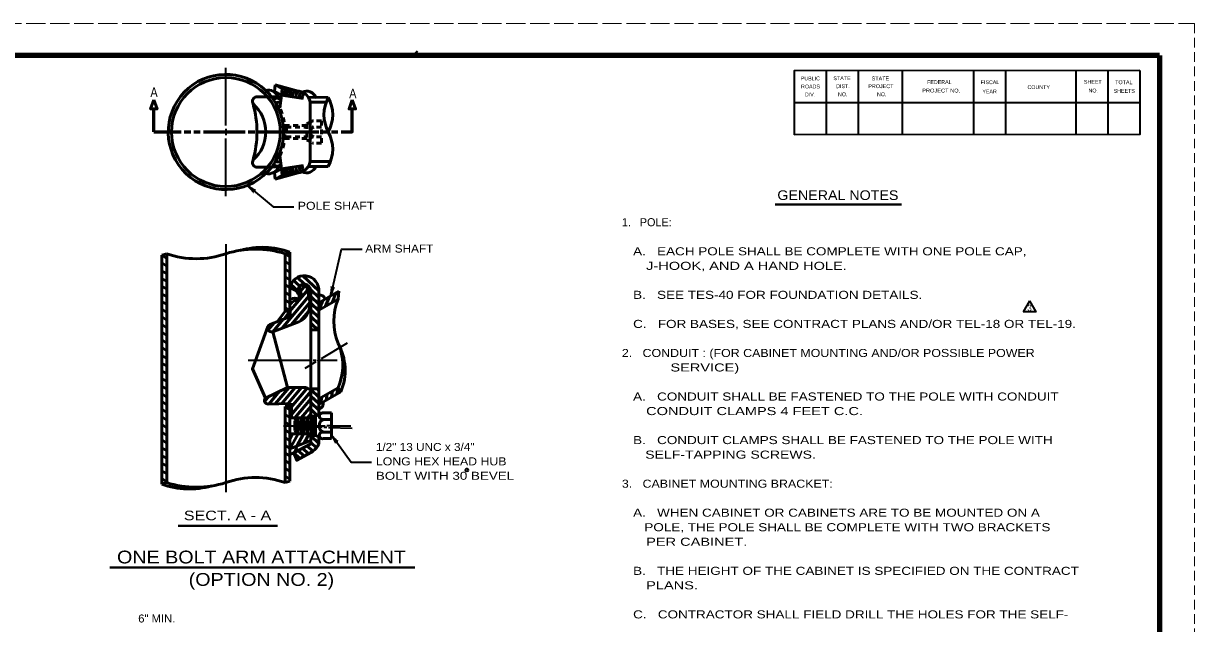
# Model space of a CAD drawing. Extents: x 6488 to 7168, y 276 to 716.
# Drawn here: x 6801.8 to 7167.7, y 528.6 to 716 of the extents above; entities that cross this region are included whole.
import ezdxf
from ezdxf.enums import TextEntityAlignment as Align

# ---------------------------------------------------------------- set-up
doc = ezdxf.new("R2010")
doc.units = 0
for name, pattern in [('LONG_DASHED', [7.5, 6, -1.5]), ('MEDIUM_DASHED', [4.5, 3, -1.5]), ('SHORT_DASHED', [2.7, 1.5, -1.2])]:
    doc.linetypes.add(name, pattern=pattern)
doc.layers.add('1', color=7, linetype='Continuous', lineweight=35)
doc.layers.add('61', color=7, linetype='Continuous', lineweight=35)

msp = doc.modelspace()

# ---------------------------------------------------------------- linework, layer by layer
at = {"layer": '1', "linetype": 'MEDIUM_DASHED', "lineweight": 13}
msp.add_line((7167.663, 716.04), (7167.643, 276.02), dxfattribs=at)
at = {"layer": '1', "linetype": 'SHORT_DASHED', "lineweight": 53}
for p, q in [((6924.843, 706.832), (6924.405, 707.27)), ((6890.36, 684.641), (6891.606, 685.264)), ((6890.36, 684.641), (6890.36, 679.641)), ((6894.86, 685.641), (6892.36, 685.641)), ((6894.86, 685.641), (6894.86, 678.641)), ((6883.402, 684.141), (6882.964, 683.703)), ((6883.402, 684.141), (6890.36, 684.141)), ((6883.951, 683.641), (6890.36, 683.641)), ((6883.951, 683.641), (6883.953, 680.641)), ((6883.953, 680.641), (6890.36, 680.641)), ((6894.86, 683.641), (6892.36, 683.641)), ((6894.86, 680.641), (6892.36, 680.641)), ((6883.405, 680.141), (6890.36, 680.141)), ((6890.36, 679.641), (6891.606, 679.018)), ((6894.86, 678.641), (6892.36, 678.641))]:
    msp.add_line(p, q, dxfattribs=at)
at = {"layer": '1'}
for p, q in [((6865.036, 684.141), (6865.036, 702.127)), ((6865.036, 683.141), (6865.036, 681.141)), ((6865.036, 662.127), (6865.036, 680.141)), ((6865.036, 647.127), (6865.036, 569.627)), ((7116.109, 629.377), (7114.109, 625.913)), ((6894.956, 611.435), (6903.03, 616.279)), ((6893.67, 610.663), (6894.527, 611.178)), ((6872.026, 610.877), (6891.776, 610.877)), ((6889.811, 608.348), (6893.241, 610.406)), ((6892.276, 610.877), (6893.276, 610.877)), ((6893.776, 610.877), (6899.776, 610.877)), ((6883.036, 590.377), (6896.026, 590.377)), ((6883.036, 590.377), (6895.084, 589.957)), ((6895.584, 589.939), (6896.587, 589.904)), ((6897.526, 590.377), (6896.526, 590.377)), ((6897.086, 589.887), (6904.526, 589.627)), ((6898.026, 590.377), (6904.026, 590.377))]:
    msp.add_line(p, q, dxfattribs=at)
at = {"layer": '1', "lineweight": 53}
for p, q in [((6880.456, 696.846), (6880.213, 694.861)), ((6882.622, 695.596), (6880.456, 696.846)), ((6880.456, 696.846), (6887.573, 694.9)), ((6882.378, 693.611), (6882.622, 695.596)), ((6882.622, 695.596), (6887.573, 694.9)), ((6874.536, 693.141), (6878.016, 693.102)), ((6877.475, 695.136), (6877.282, 695.088)), ((6878.266, 693.1), (6879.062, 693.091)), ((6879.311, 693.088), (6882.309, 693.055)), ((6881.455, 693.064), (6879.312, 693.088)), ((6882.378, 693.611), (6880.213, 694.861)), ((6881.89, 689.641), (6882.378, 693.611)), ((6882.378, 693.611), (6889.31, 692.637)), ((6890.778, 692.961), (6897.036, 692.891)), ((6893.143, 692.934), (6890.778, 692.961)), ((6891.36, 691.399), (6891.36, 672.899)), ((6881.903, 674.641), (6882.391, 670.671)), ((6874.536, 671.141), (6878.04, 671.18)), ((6878.29, 671.183), (6879.083, 671.192)), ((6879.333, 671.194), (6882.322, 671.228)), ((6881.478, 671.21), (6879.335, 671.186)), ((6882.391, 670.671), (6880.226, 669.421)), ((6882.391, 670.671), (6889.323, 671.645)), ((6882.391, 670.671), (6882.635, 668.686)), ((6893.111, 671.325), (6890.746, 671.298)), ((6890.768, 671.322), (6897.036, 671.391)), ((6877.497, 669.135), (6877.305, 669.183)), ((6880.226, 669.421), (6880.469, 667.436)), ((6880.469, 667.436), (6887.586, 669.382)), ((6882.635, 668.686), (6880.469, 667.436)), ((6882.635, 668.686), (6887.586, 669.382)), ((6846.536, 644.127), (6845.036, 643.627)), ((6846.536, 644.127), (6846.536, 572.627)), ((6883.536, 644.127), (6885.036, 644.627)), ((6883.536, 644.127), (6883.536, 626.127)), ((6883.536, 644.127), (6885.036, 643.127)), ((6885.036, 644.627), (6885.036, 633.318)), ((6845.036, 643.627), (6845.036, 572.127)), ((6845.036, 643.627), (6846.536, 642.627)), ((6845.036, 641.223), (6846.536, 640.223)), ((6883.536, 641.723), (6885.036, 640.723)), ((6845.036, 638.819), (6846.536, 637.819)), ((6883.536, 639.319), (6885.036, 638.319)), ((6883.536, 636.916), (6885.036, 635.916)), ((6887.399, 636.72), (6889.619, 634.607)), ((6889.045, 637.224), (6894.026, 632.485)), ((6845.036, 636.416), (6846.536, 635.416)), ((6845.036, 634.012), (6846.536, 633.012)), ((6883.536, 634.512), (6885.036, 633.512)), ((6885.036, 629.651), (6885.036, 633.318)), ((6885.036, 633.318), (6885.036, 629.894)), ((6885.366, 634.513), (6887.4, 632.578)), ((6886.197, 635.793), (6888.019, 634.06)), ((6887.255, 632.238), (6888.035, 634.074)), ((6888.035, 633.824), (6888.718, 630.54)), ((6888.328, 632.415), (6889.807, 634.187)), ((6890.286, 633.723), (6891.186, 629.826)), ((6845.036, 631.608), (6846.536, 630.608)), ((6882.54, 620.795), (6890.945, 630.869)), ((6883.536, 632.108), (6885.036, 631.108)), ((6883.536, 629.704), (6885.036, 628.704)), ((6885.036, 626.127), (6890.522, 632.703)), ((6885.036, 629.752), (6885.036, 626.127)), ((6885.133, 629.733), (6885.036, 629.651)), ((6891.524, 632.796), (6894.026, 630.415)), ((6891.526, 630.723), (6894.026, 628.344)), ((6894.026, 628.781), (6900.305, 632.406)), ((6894.026, 628.781), (6894.026, 632.249)), ((6894.026, 626.472), (6900.088, 629.972)), ((6894.026, 626.472), (6895.273, 629.501)), ((6896.154, 627.7), (6897.4, 630.73)), ((6898.281, 628.929), (6899.528, 631.958)), ((6900.305, 632.406), (6900.088, 629.972)), ((6845.036, 629.204), (6846.536, 628.204)), ((6845.036, 626.801), (6846.536, 625.801)), ((6883.536, 626.127), (6881.129, 622.933)), ((6883.536, 627.301), (6885.036, 626.301)), ((6885.401, 621.881), (6891.369, 629.035)), ((6888.381, 623.112), (6890.872, 626.098)), ((6891.526, 628.652), (6894.026, 626.274)), ((6891.526, 626.582), (6894.026, 624.204)), ((6894.026, 620.377), (6894.026, 628.781)), ((6845.036, 624.397), (6846.536, 623.397)), ((6845.036, 621.993), (6846.536, 620.993)), ((6878.288, 620.381), (6880.087, 622.537)), ((6878.792, 622.044), (6884.165, 624.086)), ((6879.68, 619.708), (6882.947, 623.623)), ((6879.68, 619.707), (6887.857, 622.815)), ((6891.526, 624.512), (6894.026, 622.133)), ((6891.526, 622.441), (6894.026, 620.063)), ((6845.036, 619.589), (6846.536, 618.589)), ((6884.286, 602.377), (6879.68, 619.707)), ((6891.526, 620.377), (6894.026, 620.377)), ((6894.026, 595.587), (6894.026, 620.377)), ((6845.036, 617.186), (6846.536, 616.185)), ((6845.036, 614.782), (6846.536, 613.782)), ((6845.036, 612.378), (6846.536, 611.378)), ((6845.036, 609.974), (6846.536, 608.974)), ((6845.036, 607.57), (6846.536, 606.57)), ((6845.036, 605.167), (6846.536, 604.166)), ((6845.036, 602.763), (6846.536, 601.763)), ((6845.036, 600.359), (6846.536, 599.359)), ((6884.286, 602.377), (6877.398, 599.017)), ((6878.439, 597.147), (6881.785, 601.157)), ((6880.451, 597.217), (6884.756, 602.377)), ((6882.463, 597.287), (6886.71, 602.377)), ((6884.286, 602.377), (6889.46, 602.377)), ((6884.475, 597.357), (6888.663, 602.377)), ((6885.536, 596.287), (6890.442, 602.168)), ((6885.536, 593.946), (6891.526, 601.126)), ((6891.526, 601.877), (6894.026, 601.877)), ((6891.526, 601.737), (6894.026, 599.359)), ((6893.555, 601.877), (6894.026, 601.429)), ((6894.026, 598.759), (6900.088, 602.259)), ((6894.026, 597.027), (6900.954, 601.027)), ((6896.678, 600.29), (6896.324, 598.354)), ((6898.383, 601.275), (6898.029, 599.338)), ((6900.088, 602.259), (6899.734, 600.323)), ((6900.088, 602.259), (6900.954, 601.027)), ((6845.036, 597.955), (6846.536, 596.955)), ((6877.175, 597.974), (6878.491, 599.551)), ((6885.036, 597.377), (6878.29, 597.141)), ((6885.536, 597.395), (6885.536, 592.877)), ((6886.597, 592.877), (6891.526, 598.784)), ((6888.551, 592.877), (6891.526, 596.443)), ((6891.526, 599.667), (6894.026, 597.288)), ((6891.526, 597.596), (6894.026, 595.218)), ((6894.026, 597.027), (6895.357, 597.795)), ((6894.026, 595.587), (6894.026, 597.027)), ((6894.974, 599.306), (6894.619, 597.37)), ((6845.036, 595.552), (6846.536, 594.552)), ((6845.036, 593.148), (6846.536, 592.148)), ((6883.536, 596.377), (6883.536, 572.627)), ((6883.536, 596.377), (6885.036, 596.377)), ((6883.536, 596.324), (6885.036, 595.324)), ((6883.536, 593.92), (6885.036, 592.92)), ((6885.036, 596.377), (6885.036, 583.127)), ((6885.036, 592.877), (6893.026, 592.877)), ((6886.526, 591.877), (6887.526, 592.877)), ((6887.526, 592.877), (6887.526, 587.877)), ((6888.526, 592.877), (6888.526, 587.877)), ((6889.526, 592.877), (6889.526, 587.877)), ((6890.505, 592.877), (6891.526, 594.101)), ((6890.526, 592.877), (6890.526, 587.877)), ((6891.526, 595.526), (6893.56, 593.591)), ((6893.026, 593.377), (6891.526, 593.377)), ((6891.526, 592.877), (6891.526, 587.877)), ((6892.526, 592.877), (6892.526, 587.877)), ((6893.026, 593.377), (6894.417, 593.933)), ((6893.026, 593.377), (6893.026, 587.377)), ((6894.026, 593.777), (6894.026, 595.587)), ((6898.026, 594.377), (6895.526, 594.377)), ((6898.026, 594.377), (6898.026, 586.377)), ((6845.036, 590.744), (6846.536, 589.744)), ((6883.536, 591.517), (6885.036, 590.517)), ((6883.536, 589.113), (6885.036, 588.113)), ((6886.526, 591.877), (6886.526, 588.877)), ((6888.026, 591.877), (6888.026, 588.877)), ((6889.026, 591.877), (6889.026, 588.877)), ((6890.026, 591.877), (6890.026, 588.877)), ((6891.026, 591.877), (6891.026, 588.877)), ((6892.026, 591.877), (6892.026, 588.877)), ((6893.026, 591.877), (6893.026, 588.877)), ((6898.026, 592.377), (6895.526, 592.377)), ((6845.036, 588.34), (6846.536, 587.34)), ((6845.036, 585.937), (6846.536, 584.937)), ((6883.536, 586.709), (6885.036, 585.709)), ((6885.036, 587.877), (6893.026, 587.877)), ((6885.036, 583.127), (6887.6, 587.877)), ((6885.036, 586.285), (6885.895, 587.877)), ((6885.036, 583.127), (6891.526, 585.749)), ((6886.526, 588.877), (6887.526, 587.877)), ((6887.216, 584.008), (6889.305, 587.877)), ((6889.396, 584.889), (6891.009, 587.877)), ((6891.526, 584.749), (6891.526, 587.877)), ((6893.026, 587.377), (6891.526, 587.377)), ((6891.526, 587.244), (6894.026, 584.866)), ((6893.026, 587.377), (6894.369, 586.84)), ((6894.026, 584.749), (6894.026, 586.977)), ((6898.026, 588.377), (6895.526, 588.377)), ((6898.026, 586.377), (6895.526, 586.377)), ((6845.036, 583.533), (6846.536, 582.533)), ((6883.536, 584.305), (6885.036, 583.305)), ((6883.536, 581.902), (6885.036, 580.901)), ((6885.036, 583.127), (6887.038, 583.936)), ((6885.036, 583.305), (6885.036, 573.127)), ((6885.036, 581.511), (6885.036, 583.127)), ((6886.228, 581.933), (6888.113, 580.14)), ((6887.624, 582.675), (6889.488, 580.902)), ((6889.02, 583.417), (6890.863, 581.664)), ((6890.416, 584.159), (6892.226, 582.438)), ((6891.526, 585.174), (6893.315, 583.472)), ((6845.036, 581.129), (6846.536, 580.129)), ((6845.036, 578.725), (6846.536, 577.725)), ((6883.536, 579.498), (6885.036, 578.498)), ((6845.036, 576.322), (6846.536, 575.321)), ((6883.536, 577.094), (6885.036, 576.094)), ((6883.536, 574.69), (6885.036, 573.69)), ((6845.036, 573.918), (6846.536, 572.918)), ((6846.536, 572.627), (6845.036, 572.127)), ((6883.536, 572.627), (6885.036, 573.127))]:
    msp.add_line(p, q, dxfattribs=at)
at = {"layer": '1', "lineweight": 60}
for p, q in [((6842.534, 682.141), (6842.534, 689.322)), ((6842.534, 682.141), (6851.034, 682.141)), ((6852.034, 682.141), (6854.034, 682.141)), ((6855.034, 682.141), (6857.034, 682.141)), ((6858.034, 682.141), (6871.034, 682.141)), ((6872.034, 682.141), (6874.034, 682.141)), ((6875.034, 682.141), (6877.034, 682.141)), ((6878.034, 682.141), (6894.034, 682.141)), ((6895.034, 682.141), (6897.034, 682.141)), ((6898.034, 682.141), (6900.034, 682.141))]:
    msp.add_line(p, q, dxfattribs=at)
at = {"layer": '1', "linetype": 'LONG_DASHED', "lineweight": 53}
for p, q in [((6896.36, 691.399), (6891.36, 691.399)), ((6897.717, 672.899), (6891.36, 672.899))]:
    msp.add_line(p, q, dxfattribs=at)
at = {"layer": '1', "lineweight": 40}
for p, q in [((7036.624, 659.512), (7076.064, 659.512)), ((6850.157, 559.125), (6881.136, 559.125)), ((6828.823, 546.105), (6924.037, 546.105))]:
    msp.add_line(p, q, dxfattribs=at)
at = {"layer": '1', "lineweight": 53}
for points in [[(6842.534, 692.141), (6843.56, 689.322), (6841.508, 689.322)], [(6904.534, 692.141), (6903.508, 689.322), (6905.56, 689.322)]]:
    msp.add_lwpolyline(points, close=True, dxfattribs=at)
at = {"layer": '1', "lineweight": 60}
msp.add_lwpolyline([(6901.034, 682.141), (6904.534, 682.141), (6904.534, 689.322)], dxfattribs=at)
at = {"layer": '1'}
for points in [[(6871.766, 665.433), (6879.767, 658.81), (6886.299, 658.81)], [(6897.787, 630.953), (6901.149, 645.491), (6907.608, 645.491)], [(7116.109, 629.377), (7118.109, 625.913), (7114.109, 625.913)], [(6898.026, 587.505), (6904.139, 578.964), (6910.524, 578.964)]]:
    msp.add_lwpolyline(points, dxfattribs=at)
at = {"layer": '1', "lineweight": 53}
for points in [[(6885.036, 628.258), (6885.036, 629.651), (6885.133, 629.733)], [(6891.526, 592.877), (6891.526, 620.377), (6891.526, 632.249)], [(6896.021, 629.933), (6894.026, 628.781), (6894.026, 631.105)], [(6896.021, 629.933), (6894.026, 628.781), (6894.026, 631.105)], [(6883.536, 626.127), (6885.036, 626.127), (6883.23, 623.731)], [(6877.398, 599.017), (6873.33, 608.153), (6878.105, 621.371)], [(6891.526, 584.749), (6886.228, 581.933), (6887.165, 579.615), (6891.538, 582.039)]]:
    msp.add_lwpolyline(points, dxfattribs=at)
msp.add_circle((6865.034, 682.127), 17, dxfattribs=at)
at = {"layer": '1'}
msp.add_circle((6940.276, 576.56), 0.437, dxfattribs=at)
at = {"layer": '1', "lineweight": 53}
for centre, radius, start, end in [((6865.034, 682.127), 18, 46.29439, 46.29432), ((6878.215, 691.707), 3.512, 22.73321, 102.24022), ((6884.611, 693.742), 1.627, 117.67481, 178.09117), ((6874.924, 691.622), 1.568, 104.31597, 207.75905), ((6865.034, 682.127), 18, 37.51322, 46.29439), ((6881.024, 690.83), 1.87, 59.13184, 120.50976), ((6885.482, 693.614), 1.627, 117.67481, 178.09117), ((6886.416, 693.388), 1.627, 117.67481, 178.09117), ((6887.415, 693.259), 1.627, 117.67481, 178.09117), ((6888.511, 693.162), 1.627, 117.67481, 178.09117), ((6887.256, 690.759), 4.154, 66.70777, 85.61624), ((6889.607, 693.065), 1.627, 126.56498, 178.09117), ((6890.477, 692.775), 1.627, 130.83621, 173.17119), ((6890.246, 691.749), 3.13, 22.24909, 115.50855), ((6887.256, 690.759), 4.154, 32.00963, 66.70778), ((6887.256, 690.759), 4.154, 8.85834, 66.70714), ((6906.919, 687.514), 11.251, 151.4518, 208.52599), ((6887.148, 687.514), 11.251, 331.47401, 28.5482), ((6865.909, 682.141), 11.607, 311.07568, 48.92433), ((6842.526, 682.141), 32.22, 344.24246, 15.75754), ((6881.46, 690.23), 1.196, 70.78315, 120.86396), ((6881.595, 689.776), 0.281, 74.21707, 117.92319), ((6887.151, 676.764), 11.251, 331.47401, 28.5482), ((6874.924, 672.661), 1.568, 152.24095, 255.68403), ((6881.595, 674.412), 0.281, 242.07681, 285.78293), ((6878.239, 672.567), 3.512, 257.75978, 337.26679), ((6865.057, 682.147), 18, 313.70561, 322.48678), ((6881.024, 673.358), 1.87, 239.49024, 300.86816), ((6881.46, 673.958), 1.196, 239.13604, 289.21685), ((6884.611, 670.51), 1.627, 181.90883, 242.32519), ((6885.482, 670.639), 1.627, 181.90883, 242.32519), ((6886.416, 670.864), 1.627, 181.90883, 242.32519), ((6887.415, 670.993), 1.627, 181.90883, 242.32519), ((6888.511, 671.09), 1.627, 181.90883, 242.32519), ((6887.256, 673.538), 4.154, 274.38376, 351.14166), ((6889.607, 671.187), 1.627, 181.90883, 233.43502), ((6890.477, 671.477), 1.627, 186.82881, 229.16379), ((6890.214, 672.51), 3.13, 244.49145, 337.75091), ((6887.224, 673.5), 4.154, 293.29223, 327.99037), ((6855.786, 670.387), 27.841, 250.595, 289.40499), ((6874.286, 615.086), 30.478, 72.33239, 107.66762), ((6876.465, 620.646), 25.467, 70.33208, 105.78399), ((6889.524, 632.722), 4.527, 354.00383, 172.43749), ((6884.874, 630.166), 3.156, 352.12634, 87.06139), ((6889.442, 632.514), 2.101, 352.76664, 132.03252), ((6889.126, 633.003), 1.366, 31.83455, 143.01959), ((6887.884, 626.251), 3.484, 88.08418, 144.83546), ((6886.567, 627.946), 2.292, 51.26202, 128.73798), ((6886.567, 627.946), 2.292, 51.26202, 128.73798), ((6884.994, 628.47), 6.339, 296.85326, 12.34881), ((6894.525, 629.67), 1.519, 9.96701, 109.19406), ((6894.525, 629.67), 1.519, 9.96701, 109.19406), ((6917.956, 623.044), 19.164, 158.80598, 201.19401), ((6883.663, 625.507), 1.507, 289.47536, 24.31453), ((6879.42, 620.946), 1.266, 119.78112, 281.82632), ((6884.947, 607.677), 17.334, 337.43907, 29.13126), ((6884.28, 609.26), 17.289, 336.11327, 17.19125), ((6889.373, 599.563), 2.815, 40.11472, 91.77534), ((6878.276, 598.285), 1.144, 140.1661, 270.70249), ((6893.667, 597.309), 1.759, 281.77703, 16.07576), ((6895.283, 593.377), 1.029, 76.31896, 283.68104), ((6896.263, 590.377), 2.132, 110.23854, 249.76146), ((6895.255, 587.377), 1.036, 74.83777, 285.16224), ((6884.919, 583.647), 2.139, 273.13893, 7.7568), ((6889.427, 586.474), 4.912, 295.45694, 339.44803), ((6853.607, 596.108), 25.467, 250.33208, 285.78399), ((6855.786, 601.668), 30.478, 252.33239, 287.66762), ((6874.286, 546.368), 27.841, 70.595, 109.40499)]:
    msp.add_arc(centre, radius, start, end, dxfattribs=at)
at = {"layer": '1', "linetype": 'SHORT_DASHED', "lineweight": 53}
for centre, radius, start, end in [((6865.315, 682.127), 18.199, 335.7124, 24.38628), ((6892.388, 684.641), 1, 91.64956, 268.35044), ((6892.388, 679.641), 1, 91.64956, 268.35044), ((6893.073, 682.141), 1.661, 115.42575, 244.57425)]:
    msp.add_arc(centre, radius, start, end, dxfattribs=at)
at = {"layer": '1', "lineweight": 40}
for centre, major_axis, ratio, start_param, end_param in [((6872.494, 664.556), (1.241, -1.255), 0.07063, 6.2823074, 8.5597026), ((6872.782, 664.95), (-1.475, 1.018), 0.122415, 0.8963533, 3.1415927), ((6897.764, 632.078), (-0.25, -1.775), 0.122415, 0.8963533, 3.1415927), ((6898.246, 631.997), (0.567, 1.672), 0.07063, 6.2823074, 8.5597026), ((6898.506, 586.471), (0.879, -1.531), 0.07063, 6.2823074, 8.5597026), ((6898.886, 586.778), (-1.166, 1.361), 0.122415, 0.8963533, 3.1415927)]:
    msp.add_ellipse(centre, major_axis=major_axis, ratio=ratio, start_param=start_param, end_param=end_param, dxfattribs=at)
at = {"layer": '61', "linetype": 'LONG_DASHED', "lineweight": 13}
msp.add_line((6487.643, 716.04), (7167.663, 716.04), dxfattribs=at)
at = {"layer": '61', "lineweight": 158}
msp.add_line((7156.683, 706.04), (7156.703, 286), dxfattribs=at)
at = {"layer": '61'}
for p, q in [((7052.603, 701.28), (7052.603, 681.28)), ((7062.603, 701.28), (7062.603, 681.28)), ((7076.283, 701.28), (7076.283, 681.28)), ((7098.603, 701.28), (7098.603, 681.28)), ((7108.603, 701.28), (7108.603, 681.28)), ((7130.583, 701.3), (7130.583, 681.3)), ((7140.583, 701.3), (7140.583, 681.3)), ((7150.603, 691.26), (7042.583, 691.28))]:
    msp.add_line(p, q, dxfattribs=at)
at = {"layer": '61', "lineweight": 158}
msp.add_lwpolyline([(7156.683, 706.04), (6517.643, 706.04), (6517.643, 286.02)], dxfattribs=at)
at = {"layer": '61'}
for points in [[(7150.583, 701.3), (7042.603, 701.28), (7042.603, 681.28)], [(7150.583, 701.3), (7150.583, 681.3), (7042.603, 681.28)]]:
    msp.add_lwpolyline(points, dxfattribs=at)

# ---------------------------------------------------------------- texts
at = {"layer": '1'}
for s, height, width, p in [('A', 3, 0.85, (6841.45, 693.059)), ('A', 3, 0.85, (6903.558, 692.672)), ('GENERAL NOTES', 3.024, 1.1, (7037.324, 660.892)), ('POLE SHAFT', 2.5, 1.15, (6887.499, 657.834)), ('ARM SHAFT', 2.5, 1.1, (6908.589, 644.479)), ('   A.   EACH POLE SHALL BE COMPLETE WITH ONE POLE CAP,', 2.52, 1.25, (6988.744, 643.612)), ('      J-HOOK, AND A HAND HOLE.', 2.52, 1.35, (6988.744, 639.072)), ('   B.   SEE TES-40 FOR FOUNDATION DETAILS.', 2.52, 1.25, (6988.744, 630.012)), ('3', 2, 0.9, (7115.441, 626.181)), ('   C.   FOR BASES, SEE CONTRACT PLANS AND/OR TEL-18 OR TEL-19.', 2.52, 1.25, (6988.744, 620.932)), ('2.   CONDUIT : (FOR CABINET MOUNTING AND/OR POSSIBLE POWER', 2.52, 1.15, (6988.744, 611.852)), ('            SERVICE)', 2.52, 1.35, (6988.744, 607.332)), ('   A.   CONDUIT SHALL BE FASTENED TO THE POLE WITH CONDUIT', 2.52, 1.25, (6988.744, 598.252)), ('      CONDUIT CLAMPS 4 FEET C.C.', 2.52, 1.35, (6988.744, 593.712)), ('   B.   CONDUIT CLAMPS SHALL BE FASTENED TO THE POLE WITH', 2.52, 1.25, (6988.744, 584.652)), ('1/2" 13 UNC x 3/4"', 2.5, 1.1, (6911.894, 582.511)), ('      SELF-TAPPING SCREWS.', 2.52, 1.3, (6988.744, 580.112)), ('LONG HEX HEAD HUB', 2.5, 1.15, (6911.894, 578.011)), ('BOLT WITH 30 BEVEL', 2.5, 1.25, (6911.894, 573.511)), ('3.   CABINET MOUNTING BRACKET:', 2.52, 1.15, (6988.744, 571.032)), ('SECT. A - A', 3, 1.25, (6851.898, 560.867)), ('   A.   WHEN CABINET OR CABINETS ARE TO BE MOUNTED ON A', 2.52, 1.25, (6988.744, 561.972)), ('      POLE, THE POLE SHALL BE COMPLETE WITH TWO BRACKETS', 2.52, 1.25, (6988.744, 557.432)), ('      PER CABINET.', 2.52, 1.35, (6988.744, 552.892)), ('   B.   THE HEIGHT OF THE CABINET IS SPECIFIED ON THE CONTRACT', 2.52, 1.25, (6988.744, 543.812)), ('      PLANS.', 2.52, 1.35, (6988.744, 539.292)), ('6" MIN.', 2.5, 1.05, (6837.649, 528.941)), ('   C.   CONTRACTOR SHALL FIELD DRILL THE HOLES FOR THE SELF-', 2.52, 1.25, (6988.744, 530.212))]:
    msp.add_text(s, height=height, dxfattribs=dict(at, width=width)).set_placement(p)
msp.add_text('1.   POLE:', height=2.52, dxfattribs=at).set_placement((6988.744, 652.692))
at = {"layer": '1', "width": 1.15}
for s, p in [('ONE BOLT ARM ATTACHMENT', (6876.135, 547.382)), ('(OPTION NO. 2)', (6876.134, 540.382))]:
    msp.add_text(s, height=4, dxfattribs=at).set_placement(p, align=Align.CENTER)
at = {"layer": '61'}
for s, rotation, p in [('PUBLIC', 0.033, (7044.643, 698.26)), ('ROADS', 0.124, (7044.723, 695.74)), ('DIST.', 0.056, (7055.683, 695.82)), ('FEDERAL', 0.007, (7084.103, 697.14)), ('FISCAL', 359.942, (7100.843, 697.08)), ('YEAR', 0.105, (7101.363, 694.18)), ('COUNTY', 0.069, (7115.463, 695.54)), ('SHEET', 0.059, (7133.103, 697.2)), ('SHEETS', 359.959, (7142.383, 694.36)), ('DIV.', 359.932, (7045.923, 693.24))]:
    msp.add_text(s, height=1.201, rotation=rotation, dxfattribs=at).set_placement(p)
for s, rotation, width, p in [('STATE', 0.059, 1.05, (7054.803, 698.32)), ('STATE', 0.059, 1.05, (7066.803, 698.26)), ('PROJECT', 359.908, 1.05, (7065.723, 695.84)), ('PROJECT NO.', 359.922, 1.1, (7082.563, 694.48)), ('NO.', 359.852, 0.95, (7134.523, 694.48)), ('TOTAL', 359.926, 1.05, (7142.843, 697.06)), ('NO.', 359.852, 0.95, (7056.263, 693.3)), ('NO.', 0.225, 0.95, (7068.463, 693.3))]:
    msp.add_text(s, height=1.201, rotation=rotation, dxfattribs=dict(at, width=width)).set_placement(p)

doc.saveas('drawing.dxf')
